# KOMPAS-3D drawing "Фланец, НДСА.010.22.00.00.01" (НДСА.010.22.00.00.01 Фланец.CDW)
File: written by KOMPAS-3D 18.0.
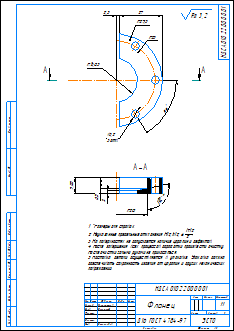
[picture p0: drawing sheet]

Sheet 1: A3, portrait

Document properties: Масса: 0; Автор: Пользователь Windows; Параметр неуказанной шероховатости: Ra 3,2; Полное имя файла: НДСА.010.22.00.00.01 Фланец.m3d; PDM_DOCXDTO: <item xmlns="http://appius.ru/pdm" xmlns:xs="http://www.w3.org/2001/XMLSchema" xmlns:xsi="http://www.w3.org/2001/XMLSchema-instance" xsi:type="item">  <element xmlns:d2p1="http://v8.1c.ru/8.1/data/enterprise/current-config" xsi:type="d2p1:CatalogRef.aps_Элемен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

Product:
- Part/product: Фланец  | designation НДСА.010.22.00.00.01
    Материал: Д16 ГОСТ 4784-97 (density 2800 kg/m3)
    Масса: 0.0195752
  - Body: Тело 1
      Масса: 0.0546706

Title block, sheet 1: Наименование: Фланец; designation: НДСА.010.22.00.00.01; Материал: Д16 ГОСТ 4784-97; scale: 1:1; sheets: 1; organisation: ЭСТО; Форматы листов документа: A3; stored path: E:\paul\Новая папка (5)\Виноградов\Новая папка\столик\Новая папка (9)\НДСА.010.09.01.01 СБ Вакуум\НДСА.010.09.01.01 Хомут.cdw; Разработал: Горностаев; Проверил: Белецкий; Утвердил: Виноградов

Views: Проекционный вид 2, Слева, Разрез А-А
Referenced files in C:\Users\Конструктор 2\Desktop\ICP\НДСА.010 Технологический модуль\НДСА.010.22 Вакуумная система\: НДСА.010.22.00.00.01 Фланец.m3d
Referenced files in E:\paul\Новая папка (5)\Виноградов\Новая папка\столик\Новая папка (9)\НДСА.010.01.01.00 СБ Камера\: односторонний хомут.m3d
Referenced files in E:\paul\Новая папка (5)\Виноградов\Новая папка\столик\Новая папка (9)\НДСА.010.09.01.01 СБ Вакуум\: НДСА.010.09.01.01 Хомут.m3d, НДСА.010.09.01.02 Хомут.m3d
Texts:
  Ra 3,2
Dimensions and other numbers on the sheet: 29,5; 13,85; 25; 5,2; 3 отв.; 27; 2,5; 20; 6,5; 2; 102; 9,85; 1:1; 1

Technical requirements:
  *Размеры для справок
  Неуказанные предельные отклонения H12, h12,    IT12 2 .
  На поверхностях не допускается наличие царапин и дефектов.
  После завершения всех процессов обработки произвести очистку.
  После очистки голыми руками не прикасаться.
  Поставка детали осуществляется в упаковке. Упаковка должна
  обеспечивать сохранность изделия от царапин и других механических
  повреждений.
